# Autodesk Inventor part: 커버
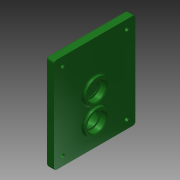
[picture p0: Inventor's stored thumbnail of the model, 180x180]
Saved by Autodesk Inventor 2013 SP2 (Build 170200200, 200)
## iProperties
Created: 2016-02
Part Number: 커버
Material: 일반
Document SubType Name: Modeling
Designer: mduedu
Density: 1 g/cm^3
Author: mduedu
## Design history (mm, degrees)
sketch "스케치1"
  geometry: L1 (63, 47)-(-47, 47); L2 (-47, 47)-(-47, -47); L3 (-47, -47)-(63, -47); L4 (63, -47)-(63, 47); 2 further points
  constraints: 8 end point, 2 parallel, 1 horizontal, 1 horizontal alignment, 1 midpoint, 1 perpendicular
  dimensions: "d102" = 94 distance of L3.end L1.start; "d104" = 47 distance from line of L2 point (0, 0); "d105" = 110 distance of L1.start L1.end
extrude "돌출1" new body sketch "스케치1" distance "d1" = 10; taper "d2" = 0 deg
sketch "스케치2"
  geometry: C1 r 14 at (0, 11); 1 further point
  constraints: 1 centre point, 1 vertical alignment
  dimensions: "d3" = 28 diameter of C1; "d6" = 11 distance of C1.centre point (0, 0)
extrude "돌출2" join sketch "스케치2" distance "d7" = 3; taper "d8" = 0 deg
sketch "스케치3"
  geometry: C1 r 14 at (0, -20); 1 further point
  constraints: 1 centre point, 1 vertical alignment
  dimensions: "d9" = 28 diameter of C1; "d10" = 20 distance of C1.centre point (0, 0)
extrude "돌출3" join sketch "스케치3" distance "d11" = 3; taper "d12" = 0 deg
hole "구멍1" diameter "d15" = 22; stored, may be unused: countersink angle "d19" = 90 deg, drill point angle "d21" = 0 deg; dims "d13" = 10, "d14" = 10, "d16" = 6, "d17" = 4, "d18" = 2, "d20" = 7
hole "구멍2" diameter "d24" = 18; stored, may be unused: countersink angle "d28" = 90 deg, drill point angle "d30" = 0 deg; dims "d22" = 10, "d23" = 10, "d25" = 6, "d26" = 4, "d27" = 2, "d29" = 1
hole "구멍3" diameter "d33" = 22; stored, may be unused: countersink angle "d37" = 90 deg, drill point angle "d39" = 0 deg; dims "d34" = 6, "d35" = 4, "d36" = 2, "d38" = 7, "d73" = 10, "d74" = 10
sketch "스케치4"
  geometry: C1 r 14 at (0, -20) reference; C2 r 18 at (0, -20); 1 further point
  constraints: 1 centre point, 1 coincident
  dimensions: "d40" = 36 diameter of C2
extrude "돌출4" join sketch "스케치4" distance "d41" = 4; taper "d42" = 0 deg
hole "구멍4" diameter "d45" = 22; stored, may be unused: countersink angle "d49" = 90 deg, drill point angle "d51" = 0 deg; dims "d43" = 10, "d44" = 10, "d46" = 6, "d47" = 4, "d48" = 2, "d50" = 7
hole "구멍5" diameter "d54" = 18; stored, may be unused: countersink angle "d58" = 90 deg, drill point angle "d60" = 0 deg; dims "d55" = 6, "d56" = 4, "d57" = 2, "d59" = 7, "d116" = 10, "d117" = 10
fillet "모깎기1" dims "d61" = 0.3
fillet "모깎기2" dims "d62" = 2
chamfer "모따기1" distance "d63" = 1; stored, may be unused: second distance "d64" = 2, angle "d65" = 45 deg
fillet "모깎기6" dims "d88" = 2
fillet "모깎기4" dims "d75" = 2
sketch "스케치9"
  geometry: L1 (47, 63)-(47, -47) reference; L2 (-47, 63)-(47, 63) reference; L3 (-47, -47)-(-47, 63) reference; L4 (47, -47)-(-47, -47) reference; L5 (37, 53)-(37, -37); L6 (37, -37)-(-37, -37); L7 (-37, -37)-(-37, 53); L8 (-37, 53)-(37, 53); C1 r 20 at (0, -20) reference; 5 further points
  constraints: 8 end point, 4 coincident, 3 other
  dimensions: "d107" = 10 distance between parallel lines of L8 L2
hole "구멍7" sketch "스케치9" at (-37, 53), (37, 53), (37, -37), (-37, -37) diameter "d108" = 4.5; stored, may be unused: countersink angle "d112" = 90 deg, drill point angle "d114" = 118 deg; dims "d109" = 6, "d110" = 8, "d111" = 4.6, "d113" = 8
fillet "모깎기8" dims "d106" = 3
fillet "모깎기9" dims "d115" = 3
node "솔리드1"
node "투영된 루프2"
